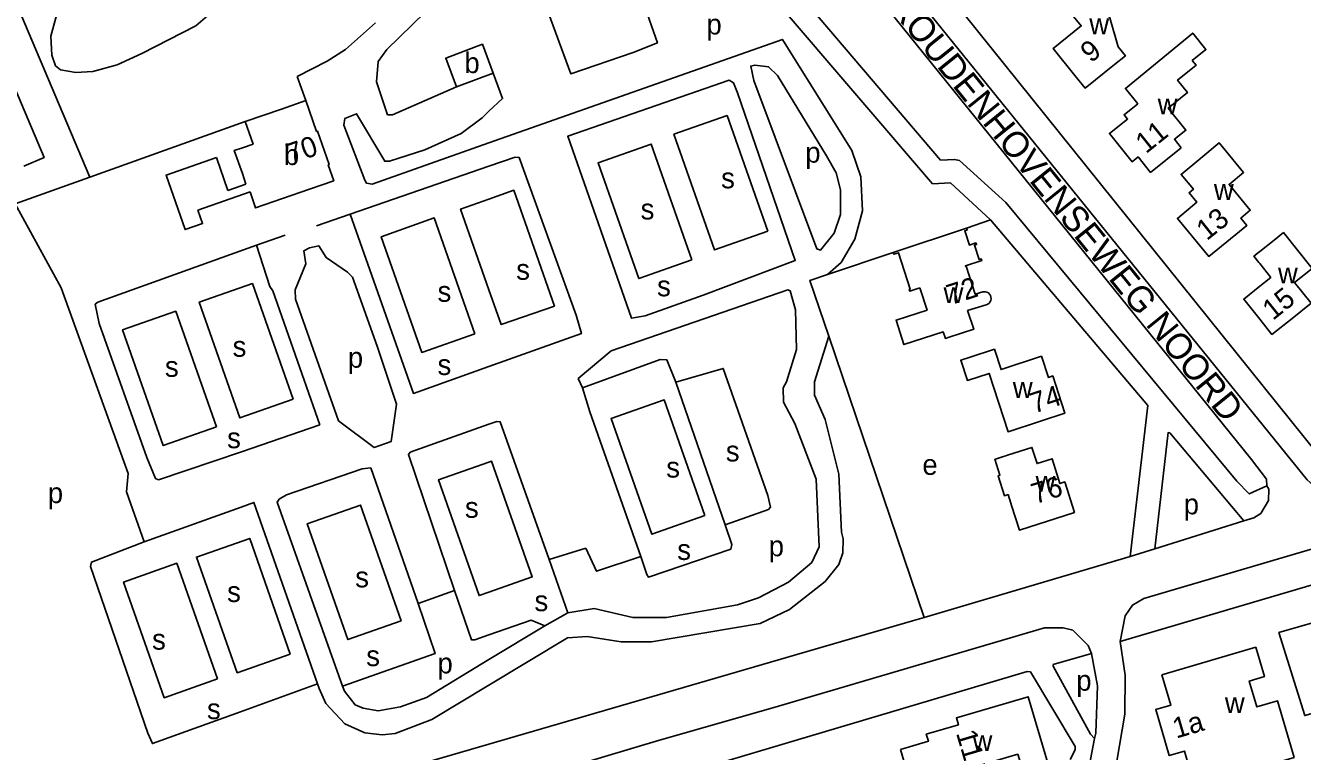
# Model space of a CAD drawing. Extents: x 162427 to 165104, y 384242 to 386287.
# Drawn here: x 163259.8 to 163508.3, y 384709.2 to 384850.5 of the extents above; entities that cross this region are included whole.
import ezdxf

# ---------------------------------------------------------------- set-up
doc = ezdxf.new("R2010")
doc.units = 0
for name, color, linetype in [('BLT_Basislijn', 7, 'Continuous'), ('BLT_Bebouwing', 7, 'Continuous'), ('BLT_Centroide', 7, 'Continuous'), ('BLT_Huisnummer', 7, 'Continuous'), ('BLT_Straatnaam', 7, 'Continuous')]:
    doc.layers.add(name, color=color, linetype=linetype)

msp = doc.modelspace()

# ---------------------------------------------------------------- linework, layer by layer
at = {"layer": 'BLT_Basislijn'}
for p, q in [((163417.99, 384883.24), (163514.84, 384762.64)), ((163247.18, 384880.45), (163272.3, 384821.01)), ((163314.35, 384835.93), (163312.65, 384840.6)), ((163302.58, 384831.82), (163272.3, 384821.01)), ((163322.96, 384813.81), (163350, 384823.16)), ((163272.3, 384821.01), (163257.77, 384815.82)), ((163316.45, 384811.56), (163322.96, 384813.81)), ((163447.58, 384812.71), (163442.93, 384811.06)), ((163310.35, 384809.71), (163304.77, 384807.76)), ((163304.77, 384807.76), (163273.85, 384796.7)), ((163307.33, 384799.73), (163304.77, 384807.76)), ((163428.69, 384806.36), (163415.89, 384802.05)), ((163307.91, 384798.87), (163307.33, 384799.73)), ((163317.08, 384772.84), (163307.91, 384798.87)), ((163273.85, 384796.7), (163273.38, 384796.29)), ((163273.38, 384796.29), (163274.14, 384792.54)), ((163274.14, 384792.54), (163283.41, 384766.47)), ((163416.12, 384790.06), (163434.67, 384735.32)), ((163368.18, 384780.01), (163369.63, 384775.36)), ((163369.63, 384775.36), (163379.55, 384747.17)), ((163301.81, 384767.54), (163317.08, 384772.84)), ((163283.41, 384766.47), (163285.12, 384762.37)), ((163285.7, 384762.1), (163301.81, 384767.54)), ((163285.12, 384762.37), (163285.7, 384762.1)), ((163496.92, 384754.13), (163479.56, 384748.66)), ((163368.88, 384748.84), (163361.7, 384746.59)), ((163361.7, 384746.59), (163365.32, 384736.23)), ((163434.67, 384735.32), (163474.76, 384747.2)), ((163474.76, 384747.2), (163479.56, 384748.66)), ((163343.27, 384740.55), (163336.19, 384738.05)), ((163350, 384710.67), (163432.44, 384734.66)), ((163365.32, 384736.23), (163360.88, 384733.71)), ((163432.44, 384734.66), (163434.67, 384735.32)), ((163350, 384727.12), (163360.88, 384733.71)), ((163350, 384693.71), (163454.76, 384724.78)), ((163454.76, 384724.78), (163455.42, 384724.75)), ((163455.42, 384724.75), (163464.08, 384710.23)), ((163464.08, 384709.59), (163463.13, 384707.7)), ((163464.08, 384710.23), (163464.08, 384709.59))]:
    msp.add_line(p, q, dxfattribs=at)
for points in [[(163366.48, 384878.63), (163376.58, 384885.47), (163377.15, 384885.54), (163383.26, 384873.76), (163406.49, 384854.58), (163436.33, 384819.73), (163439.79, 384819.92), (163447.58, 384812.71)], [(163412.77, 384881.27), (163509.26, 384762.09), (163511.01, 384760.54)], [(163406.91, 384878.75), (163393.06, 384872.97), (163392.27, 384871.95), (163408.94, 384858.03), (163410.92, 384856.05), (163437.89, 384824.35), (163440.6, 384824.48), (163441.54, 384824.24), (163450.57, 384816.07), (163495.55, 384761.86), (163497.96, 384759.38), (163501.4, 384760.97)], [(163406.91, 384878.75), (163407.84, 384878.3), (163498.38, 384766.08), (163501.3, 384762.25), (163501.4, 384760.97)], [(163271.58, 384873.7), (163264.76, 384848.44), (163264.93, 384844.79), (163265.64, 384842.68), (163266.64, 384841.88), (163269.62, 384841.36), (163272.9, 384841.58), (163277.62, 384842.86), (163282.44, 384845.07), (163292.96, 384850.5), (163295.22, 384852.43)], [(163352.83, 384868.05), (163356.01, 384867.59), (163356.33, 384867.27), (163365.92, 384841.15), (163378.06, 384845.27), (163382.79, 384847.15), (163379.99, 384855.09), (163384.47, 384857.07)], [(163343.71, 384838.57), (163331.24, 384833.13), (163330.27, 384833.17), (163328.11, 384839.59), (163328.42, 384843.51), (163330.13, 384845.86), (163350, 384865.28)], [(163312.65, 384840.6), (163318.52, 384843.61), (163322.09, 384845.89), (163327.91, 384851.07)], [(163415.89, 384802.05), (163418.52, 384804.4), (163421.23, 384808.94), (163422.71, 384814.49), (163422.4, 384821.11), (163420.65, 384826.2), (163407.12, 384847.83), (163350, 384827.69)], [(163350, 384833.86), (163352.64, 384836.31), (163350.84, 384841.28)], [(163415.71, 384825.15), (163417.56, 384821.84), (163418.42, 384818.56), (163418.42, 384813.73), (163417.15, 384810.13), (163414.55, 384806.82), (163413.81, 384807.05), (163401.57, 384839.8), (163400.96, 384842.64), (163401.73, 384842.83), (163404.42, 384842.52), (163406.17, 384840.83), (163415.71, 384825.15)], [(163391.66, 384798.07), (163380.4, 384794), (163377.73, 384793.55), (163365.32, 384828.99), (163396.72, 384839.88), (163397.58, 384839.4), (163398.36, 384837.4), (163409.61, 384804.79), (163391.66, 384798.07)], [(163350, 384827.69), (163327.27, 384819.68), (163326.18, 384819.84), (163325.87, 384820.44), (163321.74, 384831.14), (163321.92, 384832.43), (163324.24, 384833.36), (163329.73, 384824.13), (163330.61, 384824.13), (163337.5, 384826.31), (163344.61, 384829.54), (163348.68, 384832.56), (163350, 384833.86)], [(163404.24, 384810.5), (163396.33, 384833.01), (163385.98, 384829.37), (163393.9, 384806.86), (163404.24, 384810.5)], [(163389.51, 384804.93), (163381.59, 384827.44), (163371.25, 384823.8), (163379.16, 384801.29), (163389.51, 384804.93)], [(163350, 384823.16), (163355.1, 384824.93), (163355.9, 384824.82), (163366.95, 384794.15), (163367.99, 384790.56), (163350, 384784.16)], [(163350, 384816.76), (163344.47, 384814.82), (163350, 384799.1)], [(163350, 384799.1), (163352.39, 384792.31), (163362.73, 384795.94), (163354.82, 384818.46), (163350, 384816.76)], [(163257.77, 384815.82), (163266.76, 384799.47), (163279.8, 384763.37), (163279.45, 384759.77), (163282.92, 384750.06)], [(163350, 384784.16), (163335.3, 384778.92), (163322.96, 384813.81)], [(163347.28, 384790.55), (163339.36, 384813.07), (163329.02, 384809.43), (163336.93, 384786.92), (163347.28, 384790.55)], [(163447.58, 384812.71), (163478.24, 384776.56), (163474.76, 384747.2)], [(163328.21, 384788.13), (163332.01, 384776.85), (163330.96, 384769.55), (163327.66, 384768.42), (163320.74, 384773.62), (163312.34, 384797.28), (163312.31, 384799.09), (163314.38, 384804.18), (163313.98, 384806.68), (163315.05, 384807.24), (163316.92, 384807.65), (163318.29, 384805.36), (163322.47, 384802.55), (163323.45, 384801.54), (163328.21, 384788.13)], [(163415.89, 384802.05), (163412.44, 384800.93), (163416.12, 384790.06)], [(163311.88, 384777.8), (163303.96, 384800.31), (163293.62, 384796.67), (163301.54, 384774.16), (163311.88, 384777.8)], [(163368.18, 384780.01), (163367.38, 384781.82), (163373.78, 384787.22), (163408.14, 384799.11), (163408.62, 384798.9), (163409.67, 384795.18), (163409.83, 384787.45), (163407.92, 384781.18), (163407.28, 384780), (163407.33, 384777.2), (163409.51, 384773.07), (163413.65, 384762.25), (163414.28, 384749.04), (163412.85, 384746.02), (163408.32, 384742.16), (163402.45, 384739.12), (163398.38, 384737.75), (163384.54, 384735.29), (163378.03, 384735.3), (163370.47, 384737.04), (163365.32, 384736.23)], [(163296.97, 384772.41), (163289.05, 384794.92), (163278.7, 384791.28), (163286.62, 384768.77), (163296.97, 384772.41)], [(163350, 384722.16), (163365.29, 384731.35), (163369.1, 384731.63), (163375.72, 384730.59), (163381.61, 384730.59), (163402.77, 384734.14), (163408.47, 384736.85), (163415.42, 384742.33), (163418.12, 384745.61), (163418.87, 384747.89), (163418.94, 384750.6), (163418.64, 384751.94), (163418.1, 384763.2), (163415.4, 384773.86), (163413.33, 384778.57), (163413.35, 384781.2), (163416.12, 384790.06)], [(163386.37, 384781.09), (163384.64, 384785.44), (163383.34, 384785.5), (163368.18, 384780.01)], [(163395.99, 384753.36), (163404.43, 384756.33), (163404.82, 384756.81), (163404.26, 384759.08), (163395.58, 384783.79), (163386.37, 384781.09)], [(163386.37, 384781.09), (163395.99, 384753.36)], [(163472.81, 384730.65), (163574.26, 384760.53), (163594.34, 384768.08), (163622.19, 384780.3)], [(163392.02, 384755.16), (163384.11, 384777.67), (163373.76, 384774.03), (163381.68, 384751.52), (163392.02, 384755.16)], [(163472.81, 384730.65), (163473.82, 384735.65), (163475.22, 384737.73), (163477.45, 384738.99), (163572.13, 384766.88), (163591.82, 384774.28), (163599.37, 384777.91)], [(163343.27, 384740.55), (163334.31, 384767.05), (163334.69, 384767.47), (163350, 384772.92)], [(163350, 384772.92), (163351.56, 384773.47), (163352.18, 384773.4), (163361.7, 384746.59)], [(163496.92, 384754.13), (163482.48, 384771.27), (163482.16, 384771.32), (163479.56, 384748.66)], [(163336.19, 384738.05), (163326.98, 384764.44), (163325.29, 384764.26), (163310.62, 384759.16), (163309.16, 384758.32), (163308.78, 384757.75), (163321.49, 384721.95)], [(163350, 384765.55), (163340.15, 384762.09), (163348.07, 384739.58), (163350, 384740.26)], [(163350, 384740.26), (163358.42, 384743.22), (163350.5, 384765.73), (163350, 384765.55)], [(163496.92, 384754.13), (163498.85, 384754.74), (163500.19, 384755.57), (163501.73, 384758.11), (163501.8, 384760.26), (163501.4, 384760.97)], [(163316.64, 384722.39), (163304.26, 384757.71), (163301.78, 384756.82), (163282.92, 384750.06)], [(163332.9, 384734.67), (163324.99, 384757.18), (163314.64, 384753.55), (163322.56, 384731.03), (163332.9, 384734.67)], [(163395.99, 384753.36), (163397.26, 384749.52), (163397.05, 384748.62), (163381.04, 384743.19), (163380.72, 384743.67), (163379.55, 384747.17)], [(163316.64, 384722.39), (163301.62, 384716.98), (163284.49, 384710.77), (163283.58, 384712.78), (163272.44, 384745.24), (163272.64, 384746.1), (163282.92, 384750.06)], [(163311.34, 384728.2), (163303.43, 384750.71), (163293.08, 384747.08), (163301, 384724.56), (163311.34, 384728.2)], [(163379.55, 384747.17), (163370.92, 384744.33), (163368.88, 384748.84)], [(163297.15, 384723.35), (163289.23, 384745.86), (163278.88, 384742.22), (163286.8, 384719.71), (163297.15, 384723.35)], [(163350, 384731.95), (163347.28, 384731), (163346.58, 384730.97), (163343.27, 384740.55)], [(163336.19, 384738.05), (163339.51, 384728.3), (163321.49, 384721.95)], [(163360.88, 384733.71), (163358.19, 384734.81), (163350, 384731.95)], [(163467.29, 384728.29), (163466.62, 384729.88), (163463.6, 384732.88), (163461.75, 384733.29), (163458.1, 384733.29), (163405.24, 384717.72), (163383.2, 384711.44), (163350, 384701.49)], [(163472.81, 384730.65), (163473.79, 384724.1), (163473.75, 384716.5), (163472.19, 384707.36), (163470.68, 384702.87), (163468.99, 384699.07), (163461.96, 384685.77)], [(163321.49, 384721.95), (163321.89, 384721), (163323.94, 384718.3), (163325.53, 384717.66), (163328.44, 384717.15), (163332.75, 384717.9), (163337.86, 384719.77), (163350, 384727.12)], [(163467.29, 384728.29), (163459.83, 384726.15), (163459.78, 384725.82), (163467.09, 384712.6), (163467.84, 384711.76)], [(163467.29, 384728.29), (163468.45, 384722), (163468.1, 384712.79), (163467.84, 384711.76)], [(163350, 384722.16), (163338.88, 384715.48), (163331.72, 384712.74), (163329.24, 384712.45), (163325.82, 384712.88), (163321.95, 384714.62), (163318.24, 384718.6), (163316.96, 384721.48), (163316.64, 384722.39)], [(163350, 384601.49), (163398.95, 384618.6), (163408.24, 384623.3), (163415.49, 384627.82), (163418.9, 384630.46), (163428.44, 384638.89), (163434.81, 384646.43), (163443.08, 384659.54), (163463.9, 384700.11), (163466.78, 384706.31), (163467.84, 384711.76)], [(163350, 384710.67), (163301.55, 384696.57), (163259.29, 384683.99)]]:
    msp.add_lwpolyline(points, dxfattribs=at)
at = {"layer": 'BLT_Bebouwing'}
for p, q in [((163299.2, 384818.44), (163296.97, 384824.85)), ((163299.2, 384818.44), (163302.71, 384819.67)), ((163303.5, 384818.14), (163293.34, 384814.6)), ((163428.69, 384806.36), (163442.93, 384811.06))]:
    msp.add_line(p, q, dxfattribs=at)
for points in [[(163471.76, 384842.97), (163473.86, 384844.66), (163472.46, 384846.41), (163470.84, 384852.02), (163470.09, 384852.95), (163472.43, 384854.85), (163469.38, 384858.64), (163466.77, 384856.55), (163462.87, 384853.42), (163465.26, 384850.45), (163459.81, 384846.08), (163464.03, 384840.81), (163466, 384838.35), (163471.76, 384842.97)], [(163484.74, 384826.71), (163483.4, 384828.38), (163485.63, 384830.16), (163482.19, 384834.47), (163485.94, 384837.48), (163484, 384839.91), (163487.61, 384842.79), (163486.88, 384843.72), (163489.54, 384845.85), (163486.97, 384849.06), (163473.85, 384838.28), (163476.25, 384835.29), (163473.6, 384833.17), (163474.28, 384832.33), (163470.76, 384829.52), (163475.15, 384824.03), (163476.33, 384824.97), (163478.76, 384821.93), (163484.74, 384826.71)], [(163350.84, 384841.28), (163348.71, 384846.88), (163341.58, 384844.17), (163343.71, 384838.57)], [(163244.45, 384840), (163246.5, 384840.86), (163248.54, 384840.05), (163248.66, 384839.77), (163255.87, 384842.8), (163263.41, 384824.83), (163259.46, 384823.17)], [(163343.71, 384838.57), (163350.84, 384841.28)], [(163302.58, 384831.82), (163309.63, 384834.28), (163314.35, 384835.93)], [(163314.35, 384835.93), (163316.45, 384829.91), (163316.62, 384829.97), (163318.89, 384823.45), (163318.73, 384823.4), (163319.8, 384820.33), (163315.07, 384818.68), (163304.58, 384815.03), (163303.5, 384818.14)], [(163302.71, 384819.67), (163302.01, 384821.7), (163300.44, 384826.21), (163302.02, 384826.74), (163304.1, 384827.46), (163302.58, 384831.82)], [(163496.06, 384810.42), (163497.52, 384811.62), (163496.33, 384813.06), (163498.17, 384814.58), (163494.03, 384819.61), (163496.85, 384821.93), (163492.12, 384827.67), (163488.55, 384824.74), (163484.69, 384821.56), (163487.08, 384818.66), (163486.24, 384817.97), (163487.76, 384816.12), (163483.98, 384813), (163490.08, 384805.58), (163496.06, 384810.42)], [(163296.97, 384824.85), (163287.16, 384821.43), (163290.86, 384810.8), (163294.26, 384811.98), (163293.34, 384814.6)], [(163442.93, 384811.06), (163443.04, 384810.72), (163442.61, 384810.58), (163443.51, 384807.81), (163444.78, 384808.22), (163444.89, 384807.9), (163444.47, 384807.76), (163444.47, 384807.76), (163445.37, 384804.99), (163445.79, 384805.12), (163445.9, 384804.78), (163442.71, 384803.75), (163442.75, 384803.63), (163442.87, 384803.67)], [(163499.83, 384804.42), (163500, 384804.2), (163502.16, 384801.5), (163500, 384799.78), (163496.88, 384797.29), (163500, 384793.38), (163502.38, 384790.4), (163506.29, 384793.52), (163509.98, 384796.47), (163506.78, 384800.49), (163510.21, 384803.22), (163504.62, 384810.23), (163502.8, 384808.77), (163499.99, 384806.54), (163499.74, 384806.34), (163498.86, 384805.63), (163499.83, 384804.42)], [(163433.88, 384799.45), (163431.91, 384798.82), (163431.8, 384799.16), (163431.8, 384799.16), (163431.96, 384799.21), (163429.67, 384806.29), (163428.8, 384806.01), (163428.69, 384806.36)], [(163442.87, 384803.67), (163444.63, 384798.23), (163446.13, 384798.71)], [(163446.76, 384796.19), (163443.16, 384795.05), (163444.33, 384791.41), (163439.58, 384789.88), (163438.83, 384789.63), (163438.42, 384790.9), (163430.77, 384788.43), (163429.23, 384793.2), (163435.27, 384795.16), (163433.88, 384799.45)], [(163446.76, 384796.19), (163447.06, 384796.31), (163447.32, 384796.5), (163447.52, 384796.75), (163447.65, 384797.05), (163447.71, 384797.36), (163447.69, 384797.68), (163447.59, 384797.99), (163447.42, 384798.26), (163447.19, 384798.49), (163446.91, 384798.64), (163446.6, 384798.73), (163446.27, 384798.73), (163446.13, 384798.71)], [(163457.32, 384773.53), (163451.03, 384771.48), (163447.32, 384782.82), (163443.12, 384781.45), (163441.83, 384785.39), (163443.63, 384785.98), (163448.38, 384787.54), (163449.68, 384783.58), (163457.53, 384786.15), (163458.87, 384782.05), (163459.71, 384782.32), (163462.07, 384775.08), (163457.32, 384773.53)], [(163451.56, 384757.54), (163451.7, 384757.1), (163453.22, 384752.34), (163463.95, 384755.76), (163462.06, 384761.69), (163461.12, 384761.39), (163459.59, 384766.21), (163456.68, 384765.28), (163455.68, 384768.42), (163450.91, 384766.9), (163450.58, 384766.79), (163450.12, 384766.65), (163448.79, 384766.22), (163448.45, 384766.11), (163449.43, 384763.01), (163449.11, 384762.91), (163450.35, 384759.02), (163451.02, 384759.24), (163451.56, 384757.54)], [(163510.74, 384733.01), (163517.77, 384735.01), (163517.37, 384736.39), (163523.88, 384738.3), (163527.82, 384725.74), (163519.62, 384723.4), (163518.7, 384726.33), (163513.74, 384724.92), (163515.83, 384718.24), (163508.76, 384716.23), (163503.72, 384732.39), (163510.26, 384734.3), (163510.74, 384733.01)], [(163480.92, 384724.17), (163499.23, 384729.53), (163500.91, 384723.82), (163497.95, 384722.95), (163499.43, 384717.9), (163503.48, 384719.09), (163506.68, 384708.07), (163489.32, 384702.98), (163490.78, 384697.95)], [(163481.49, 384694.69), (163488.94, 384696.87), (163485.33, 384709.32), (163482.4, 384708.45), (163479.77, 384717.38), (163482.68, 384718.23), (163480.92, 384724.17)], [(163430.1, 384709.64), (163435.51, 384711.24), (163435.11, 384712.59), (163441.36, 384714.44), (163440.97, 384715.76), (163454.93, 384719.89), (163458.76, 384706.97), (163453.87, 384705.52), (163452.92, 384708.71), (163437.8, 384704.24), (163438.91, 384700.48), (163433.3, 384698.82), (163430.1, 384709.64)]]:
    msp.add_lwpolyline(points, dxfattribs=at)

# ---------------------------------------------------------------- texts
at = {"layer": 'BLT_Centroide'}
for s, p in [('p', (163392.33, 384848.78)), ('w', (163466.83, 384848.84)), ('b', (163345.22, 384841.27)), ('w', (163480.14, 384833.25)), ('b', (163310.09, 384823.38)), ('p', (163411.56, 384823.84)), ('s', (163395.18, 384818.85)), ('w', (163491.08, 384816.59)), ('s', (163379.52, 384812.79)), ('s', (163355.3, 384801.04)), ('w', (163503.55, 384800.36)), ('s', (163339.99, 384796.76)), ('s', (163382.72, 384797.83)), ('w', (163438.47, 384796.5)), ('s', (163300.11, 384786.07)), ('p', (163322.54, 384783.93)), ('s', (163286.94, 384782.15)), ('s', (163339.99, 384782.51)), ('w', (163451.95, 384778.05)), ('s', (163299.04, 384768.26)), ('s', (163396.1, 384765.69)), ('s', (163384.5, 384762.55)), ('e', (163434.35, 384763.07)), ('w', (163456.38, 384759.78)), ('p', (163264.15, 384757.57)), ('s', (163345.33, 384754.72)), ('p', (163485.21, 384755.39)), ('s', (163386.64, 384746.52)), ('p', (163404.44, 384747.23)), ('s', (163323.97, 384741.18)), ('s', (163299.04, 384738.33)), ('s', (163358.86, 384736.54)), ('s', (163284.44, 384729.06)), ('s', (163326.11, 384725.85)), ('p', (163339.99, 384724.43)), ('p', (163464.3, 384721.06)), ('w', (163493.22, 384716.72)), ('s', (163295.13, 384715.52)), ('w', (163444.11, 384709.34))]:
    msp.add_text(s, height=4, dxfattribs=at).set_placement(p)
at = {"layer": 'BLT_Huisnummer'}
for s, rotation, p in [('9', 38.7171, (163467.15, 384843.13)), ('11', 38.654, (163477.86, 384825.47)), ('70', 19.2044, (163311.39, 384823.49)), ('13', 38.654, (163489.7, 384808.55)), ('72', 17.9167, (163439.84, 384796.08)), ('15', 38.654, (163502.56, 384793.02)), ('74', 18.1088, (163456.07, 384774.98)), ('76', 17.6869, (163456.31, 384757.35)), ('1a', 16.3631, (163483.74, 384711.73)), ('11', 286.4887, (163440.87, 384712.82))]:
    msp.add_text(s, height=4, rotation=rotation, dxfattribs=at).set_placement(p)
at = {"layer": 'BLT_Straatnaam'}
msp.add_text('KOUDENHOVENSEWEG NOORD', height=5, rotation=308.9625, dxfattribs=at).set_placement((163427.9, 384853.84))

doc.saveas('drawing.dxf')
